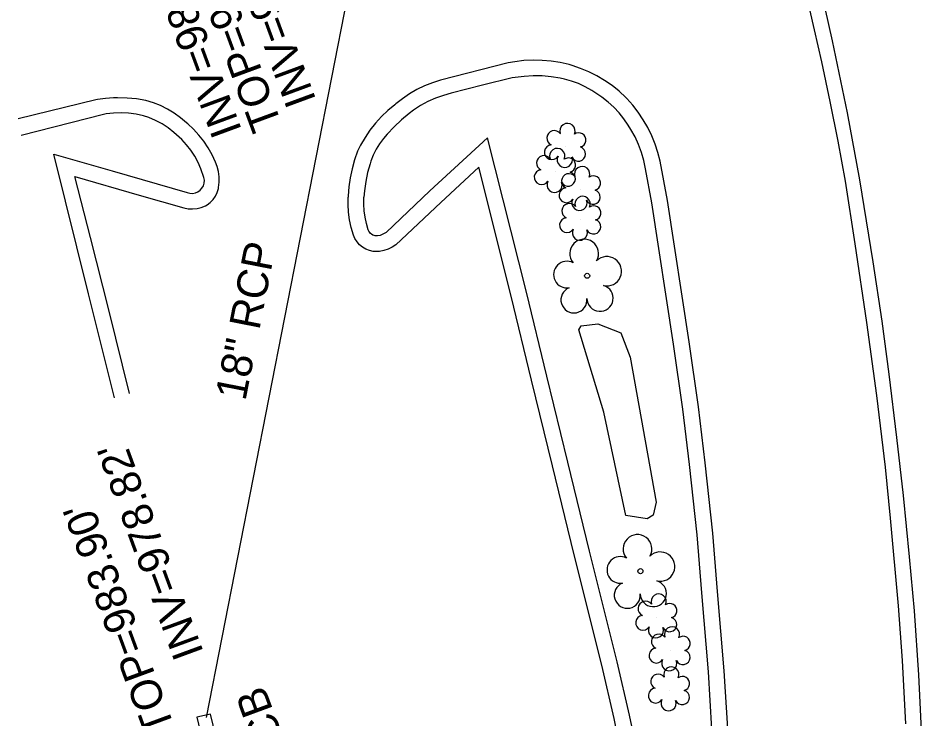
# Model space of a CAD drawing. Extents: x 1611576 to 1617186, y 899279 to 905462.
# Drawn here: x 1615784.5 to 1615902.4, y 904187.9 to 904278.6 of the extents above; entities that cross this region are included whole.
import ezdxf

# ---------------------------------------------------------------- set-up
doc = ezdxf.new("R2010")
doc.units = 0
for name, color, linetype in [('Exist Roads Curbs', 7, 'Continuous'), ('Exist Roads EOP Other', 7, 'Continuous'), ('Exist Structure Minor Catch Basin', 7, 'Continuous'), ('Exist Structure Minor Catch Basin Text', 7, 'Continuous'), ('Exist Structure Minor Catch Basin Top Elevation', 7, 'Continuous'), ('Exist Structure Minor Pipes RCP 18 Inch', 7, 'Continuous'), ('Exist Structure Minor Pipes RCP 18 Inch Invert', 7, 'Continuous'), ('Exist Structure Minor Pipes RCP 18 Inch Text', 7, 'Continuous'), ('Exist Vegetation Hedge Row', 7, 'Continuous'), ('Exist Vegetation Shrub CELL', 7, 'Continuous'), ('Exist Vegetation Tree CELL', 7, 'Continuous')]:
    doc.layers.add(name, color=color, linetype=linetype)

msp = doc.modelspace()

# ---------------------------------------------------------------- linework, layer by layer
at = {"layer": 'Exist Roads Curbs'}
for points in [[(1615893.5, 904257.65), (1615891.93, 904266.36), (1615889.96, 904275.68), (1615887.58, 904286.27), (1615885.87, 904293.7), (1615885.64, 904294.86), (1615885.5, 904296.02), (1615885.43, 904297.19), (1615885.44, 904298.37), (1615885.53, 904299.54), (1615885.57, 904299.9), (1615885.81, 904300.71), (1615886.13, 904301.49), (1615886.52, 904302.24), (1615886.98, 904302.96), (1615887.5, 904303.62), (1615887.72, 904303.86), (1615888.36, 904304.53), (1615889.06, 904305.14), (1615889.8, 904305.68), (1615890.59, 904306.16), (1615891.42, 904306.57), (1615892.28, 904306.9), (1615893.01, 904307.12)], [(1615866.57, 904254.69), (1615865.75, 904259.08), (1615865.52, 904260.15), (1615865.22, 904261.21), (1615864.84, 904262.23), (1615864.39, 904263.23), (1615863.86, 904264.2), (1615863.52, 904264.75), (1615862.96, 904265.57), (1615862.33, 904266.35), (1615861.65, 904267.08), (1615860.91, 904267.74), (1615860.11, 904268.35), (1615859.59, 904268.7), (1615858.79, 904269.24), (1615857.95, 904269.72), (1615857.08, 904270.13), (1615856.17, 904270.46), (1615855.24, 904270.71), (1615854.68, 904270.83), (1615853.52, 904271.01), (1615852.35, 904271.11), (1615851.18, 904271.12), (1615850.01, 904271.06), (1615848.85, 904270.92), (1615848.49, 904270.87), (1615844.63, 904269.92), (1615840.59, 904268.9), (1615839.56, 904268.6), (1615838.55, 904268.24), (1615837.56, 904267.79), (1615836.62, 904267.28), (1615835.71, 904266.7), (1615835.13, 904266.27), (1615834.12, 904265.42), (1615833.17, 904264.52), (1615832.27, 904263.56), (1615831.81, 904263.02), (1615831.3, 904262.34), (1615830.85, 904261.62), (1615830.47, 904260.86), (1615830.17, 904260.07), (1615830.07, 904259.75), (1615829.75, 904258.6), (1615829.51, 904257.43), (1615829.34, 904256.25), (1615829.28, 904255.4)], [(1615796.96, 904229.43), (1615793.58, 904242.9), (1615789.1, 904260.97), (1615796.65, 904258.81), (1615806.38, 904256.02), (1615806.72, 904255.92), (1615807.08, 904255.9), (1615807.44, 904255.97), (1615807.77, 904256.1), (1615808.06, 904256.31), (1615808.3, 904256.58), (1615808.48, 904256.89), (1615808.58, 904257.24), (1615808.61, 904257.6), (1615808.55, 904257.95), (1615808.16, 904259.09), (1615807.8, 904259.93), (1615807.37, 904260.73), (1615806.86, 904261.5), (1615806.3, 904262.21), (1615805.67, 904262.88), (1615805.35, 904263.17), (1615804.66, 904263.81), (1615803.91, 904264.39), (1615803.12, 904264.9), (1615802.29, 904265.35), (1615801.42, 904265.72), (1615800.71, 904265.97), (1615799.76, 904266.17), (1615798.79, 904266.3), (1615797.82, 904266.34), (1615796.85, 904266.31), (1615795.88, 904266.19), (1615795.56, 904266.14), (1615784.86, 904263.42)], [(1615864.09, 904186.33), (1615863.68, 904188.35), (1615862.07, 904195.27), (1615858.48, 904209.6), (1615855.68, 904221.11), (1615852.95, 904232.23), (1615850.32, 904243.11), (1615845.27, 904263.12), (1615837.83, 904256.23), (1615832.14, 904250.86), (1615831.91, 904250.7), (1615831.64, 904250.57), (1615831.36, 904250.47), (1615831.03, 904250.41), (1615830.95, 904250.41), (1615830.74, 904250.42), (1615830.58, 904250.46), (1615830.41, 904250.52), (1615830.27, 904250.61), (1615830.13, 904250.72), (1615830.02, 904250.85), (1615829.93, 904251), (1615829.84, 904251.21), (1615829.6, 904252), (1615829.42, 904252.83), (1615829.3, 904253.67), (1615829.26, 904254.52), (1615829.28, 904255.4)], [(1615899.79, 904096.52), (1615900.18, 904099.49), (1615900.77, 904107.74), (1615901.33, 904116.93), (1615901.83, 904128.29), (1615902.14, 904137.09), (1615902.4, 904145.94), (1615902.44, 904152.54), (1615902.38, 904160.85), (1615902.1, 904171.04), (1615901.84, 904179.09), (1615901.55, 904185.49), (1615901.14, 904193.58), (1615900.6, 904201.84), (1615899.96, 904208.86), (1615899.17, 904216.8), (1615898.31, 904224.32), (1615897.3, 904232.49), (1615896.4, 904239.36), (1615895.25, 904247.03), (1615893.5, 904257.65)], [(1615873.06, 904101.28), (1615873.63, 904112.68), (1615874.39, 904125.07), (1615875.04, 904140.12), (1615875.19, 904147.13), (1615875.17, 904162.5), (1615874.94, 904173.09), (1615874.35, 904186.53), (1615873.89, 904193.95), (1615873.05, 904204.18), (1615872.42, 904211.71), (1615871.45, 904220.8), (1615870.59, 904227.98), (1615869.39, 904236.37), (1615866.57, 904254.69)]]:
    msp.add_lwpolyline(points, dxfattribs=at)
at = {"layer": 'Exist Roads EOP Other'}
for points in [[(1615891.63, 904257.51), (1615890.68, 904262.67), (1615889.66, 904267.81), (1615888.57, 904272.93), (1615887.64, 904277.08), (1615885.33, 904287.12)], [(1615868.6, 904255), (1615867.63, 904260.06), (1615867.35, 904261.19), (1615866.98, 904262.3), (1615866.55, 904263.38), (1615866.04, 904264.43), (1615865.46, 904265.44), (1615864.81, 904266.41), (1615864.1, 904267.33), (1615863.32, 904268.2), (1615863.18, 904268.34), (1615862.32, 904269.13), (1615861.41, 904269.86), (1615860.45, 904270.52), (1615859.45, 904271.12), (1615858.41, 904271.64), (1615857.33, 904272.1), (1615856.23, 904272.48), (1615855.85, 904272.59), (1615854.7, 904272.85), (1615853.54, 904273.03), (1615852.36, 904273.13), (1615851.18, 904273.15), (1615850, 904273.1), (1615848.83, 904272.96), (1615847.96, 904272.81), (1615839.19, 904270.56), (1615838.14, 904270.23), (1615837.12, 904269.82), (1615836.13, 904269.34), (1615835.18, 904268.79), (1615834.27, 904268.17), (1615833.4, 904267.49), (1615833.26, 904267.37), (1615832.38, 904266.64), (1615831.55, 904265.85), (1615830.78, 904265), (1615830.06, 904264.1), (1615829.42, 904263.15), (1615828.84, 904262.16), (1615828.45, 904261.37), (1615828.05, 904260.25), (1615827.73, 904259.1), (1615827.49, 904257.94), (1615827.33, 904256.76), (1615827.24, 904255.58), (1615827.24, 904255.44)], [(1615798.89, 904229.99), (1615796.23, 904240.82), (1615793.88, 904250.2), (1615791.83, 904258.09), (1615800.18, 904255.69), (1615805.95, 904254.02), (1615806.51, 904253.92), (1615807.09, 904253.9), (1615807.66, 904253.96), (1615808.21, 904254.09), (1615808.75, 904254.31), (1615808.96, 904254.42), (1615809.37, 904254.74), (1615809.73, 904255.12), (1615810.03, 904255.56), (1615810.26, 904256.03), (1615810.42, 904256.53), (1615810.45, 904256.67), (1615810.52, 904257.36), (1615810.51, 904258.05), (1615810.42, 904258.73), (1615810.25, 904259.4), (1615810.04, 904259.96), (1615809.61, 904260.89), (1615809.11, 904261.79), (1615808.54, 904262.65), (1615807.9, 904263.46), (1615807.21, 904264.22), (1615806.46, 904264.92), (1615806.28, 904265.06), (1615805.52, 904265.71), (1615804.7, 904266.3), (1615803.84, 904266.82), (1615802.94, 904267.27), (1615802, 904267.65), (1615801.04, 904267.95), (1615801.04, 904267.95), (1615799.82, 904268.15), (1615798.59, 904268.26), (1615797.35, 904268.3), (1615796.83, 904268.29), (1615795.8, 904268.21), (1615794.78, 904268.06), (1615794.53, 904268.01), (1615784.5, 904265.55)], [(1615862.08, 904185.96), (1615861.68, 904187.92), (1615860.09, 904194.8), (1615856.5, 904209.11), (1615853.7, 904220.63), (1615850.97, 904231.74), (1615848.34, 904242.62), (1615844.14, 904259.29), (1615839.22, 904254.75), (1615833.42, 904249.26), (1615832.94, 904248.94), (1615832.42, 904248.68), (1615831.86, 904248.5), (1615831.29, 904248.39), (1615830.97, 904248.37), (1615830.47, 904248.39), (1615829.98, 904248.5), (1615829.52, 904248.68), (1615829.09, 904248.94), (1615828.7, 904249.26), (1615828.38, 904249.63), (1615828.11, 904250.05), (1615827.92, 904250.51), (1615827.91, 904250.52), (1615827.62, 904251.49), (1615827.41, 904252.48), (1615827.27, 904253.47), (1615827.22, 904254.48), (1615827.24, 904255.44)], [(1615899.48, 904187.22), (1615899.03, 904195.42), (1615898.52, 904202.52), (1615897.47, 904213.87), (1615896.81, 904220.44), (1615895.69, 904229.74), (1615894.41, 904239.18), (1615892.92, 904249.38), (1615891.63, 904257.51)], [(1615876.39, 904186.64), (1615875.93, 904194.1), (1615875.09, 904204.35), (1615874.45, 904211.91), (1615873.48, 904221.03), (1615872.62, 904228.25), (1615871.41, 904236.67), (1615868.6, 904255)]]:
    msp.add_lwpolyline(points, dxfattribs=at)
at = {"layer": 'Exist Structure Minor Catch Basin'}
msp.add_lwpolyline([(1615808.34, 904185.18), (1615810.09, 904185.63), (1615809.39, 904188.47), (1615807.64, 904188.07), (1615808.34, 904185.18)], dxfattribs=at)
at = {"layer": 'Exist Structure Minor Pipes RCP 18 Inch'}
msp.add_line((1615808.87, 904188.06), (1615829.26, 904292.17), dxfattribs=at)
msp.add_line((1615808.87, 904188.06), (1615829.26, 904292.17), dxfattribs=at)
at = {"layer": 'Exist Vegetation Hedge Row'}
msp.add_lwpolyline([(1615863.2, 904214.21), (1615860.34, 904227.56), (1615857.1, 904238.23), (1615857.41, 904238.76), (1615859.56, 904239.03), (1615862.53, 904237.85), (1615863.78, 904234.7), (1615867.11, 904215.91), (1615866.72, 904214.24), (1615865.98, 904213.77), (1615863.2, 904214.21)], dxfattribs=at)
at = {"layer": 'Exist Vegetation Shrub CELL'}
for p, q in [((1615855.41, 904261.95), (1615855.41, 904261.95)), ((1615854.09, 904258.71), (1615854.09, 904258.71)), ((1615857.31, 904256.37), (1615857.31, 904256.37)), ((1615857.37, 904252.5), (1615857.37, 904252.5)), ((1615867.22, 904201.01), (1615867.22, 904201.01)), ((1615868.95, 904196.76), (1615868.95, 904196.76)), ((1615868.86, 904191.57), (1615868.86, 904191.57))]:
    msp.add_line(p, q, dxfattribs=at)
for centre, radius, start, end in [((1615855.64, 904263.99), 0.99, 334.8391, 200.4717), ((1615853.93, 904263.07), 0.968, 35.8908, 245.4216), ((1615857.09, 904262.82), 0.929, 284.4567, 126.0861), ((1615853.61, 904261.24), 0.955, 95.1099, 327.9534), ((1615857.05, 904261.02), 0.937, 204.9913, 73.4601), ((1615852.61, 904259.83), 0.968, 35.8908, 245.4216), ((1615854.32, 904260.75), 0.99, 334.8391, 200.4717), ((1615855.29, 904260.26), 0.984, 151.2797, 21.387), ((1615855.76, 904259.57), 0.929, 284.4567, 126.0861), ((1615852.29, 904258), 0.955, 95.1099, 327.9534), ((1615855.83, 904257.49), 0.968, 35.8908, 245.4216), ((1615855.73, 904257.78), 0.937, 204.9913, 73.4601), ((1615857.54, 904258.41), 0.99, 334.8391, 200.4717), ((1615853.96, 904257.02), 0.984, 151.2797, 21.387), ((1615858.99, 904257.24), 0.929, 284.4567, 126.0861), ((1615855.51, 904255.66), 0.955, 95.1099, 327.9534), ((1615858.95, 904255.44), 0.937, 204.9913, 73.4601), ((1615857.19, 904254.68), 0.984, 151.2797, 21.387), ((1615857.6, 904254.54), 0.99, 334.8391, 200.4717), ((1615855.89, 904253.63), 0.968, 35.8908, 245.4216), ((1615859.04, 904253.37), 0.929, 284.4567, 126.0861), ((1615855.57, 904251.8), 0.955, 95.1099, 327.9534), ((1615859.01, 904251.58), 0.937, 204.9913, 73.4601), ((1615857.24, 904250.82), 0.984, 151.2797, 21.387), ((1615867.45, 904203.05), 0.99, 334.8391, 200.4717), ((1615865.74, 904202.14), 0.968, 35.8908, 245.4216), ((1615868.89, 904201.88), 0.929, 284.4567, 126.0861), ((1615865.42, 904200.31), 0.955, 95.1099, 327.9534), ((1615868.86, 904200.08), 0.937, 204.9913, 73.4601), ((1615867.09, 904199.33), 0.984, 151.2797, 21.387), ((1615869.18, 904198.8), 0.99, 334.8391, 200.4717), ((1615867.47, 904197.88), 0.968, 35.8908, 245.4216), ((1615870.62, 904197.63), 0.929, 284.4567, 126.0861), ((1615867.15, 904196.05), 0.955, 95.1099, 327.9534), ((1615870.59, 904195.83), 0.937, 204.9913, 73.4601), ((1615868.82, 904195.07), 0.984, 151.2797, 21.387), ((1615869.09, 904193.61), 0.99, 334.8391, 200.4717), ((1615867.38, 904192.7), 0.968, 35.8908, 245.4216), ((1615870.53, 904192.44), 0.929, 284.4567, 126.0861), ((1615867.06, 904190.87), 0.955, 95.1099, 327.9534), ((1615870.5, 904190.65), 0.937, 204.9913, 73.4601), ((1615868.73, 904189.89), 0.984, 151.2797, 21.387)]:
    msp.add_arc(centre, radius, start, end, dxfattribs=at)
at = {"layer": 'Exist Vegetation Tree CELL'}
for p, q in [((1615858.19, 904245.24), (1615858.19, 904245.24)), ((1615865.09, 904206.99), (1615865.09, 904206.99))]:
    msp.add_line(p, q, dxfattribs=at)
for centre in [(1615858.19, 904245.24), (1615865.09, 904206.99)]:
    msp.add_circle(centre, 0.326, dxfattribs=at)
for centre, radius, start, end in [((1615857.8, 904248.12), 1.86, 330.1651, 219.7134), ((1615860.74, 904245.83), 1.9, 257.1011, 134.1999), ((1615855.58, 904245.4), 1.73, 62.6636, 279.3457), ((1615856.48, 904242.12), 1.69, 111.5671, 6.231), ((1615859.86, 904242.34), 1.7, 181.2822, 74.56), ((1615864.71, 904209.87), 1.86, 330.1651, 219.7134), ((1615862.49, 904207.15), 1.73, 62.6636, 279.3457), ((1615867.64, 904207.58), 1.9, 257.1011, 134.1999), ((1615863.39, 904203.87), 1.69, 111.5671, 6.231), ((1615866.76, 904204.09), 1.7, 181.2822, 74.56)]:
    msp.add_arc(centre, radius, start, end, dxfattribs=at)

# ---------------------------------------------------------------- texts
at = {"layer": 'Exist Structure Minor Catch Basin Text'}
msp.add_text('CB', height=4, rotation=110.2165, dxfattribs=at).set_placement((1615818.87, 904185.39))
at = {"layer": 'Exist Structure Minor Catch Basin Top Elevation'}
for s, p in [("TOP=985.69'", (1615818.69, 904264.82)), ("TOP=983.90'", (1615804.83, 904186.68))]:
    msp.add_text(s, height=4, rotation=110.2165, dxfattribs=at).set_placement(p)
at = {"layer": 'Exist Structure Minor Pipes RCP 18 Inch Invert'}
for s, p in [("INV=981.20'", (1615823.12, 904267.99)), ("INV=980.90'", (1615813.5, 904264.07)), ("INV=978.82'", (1615808.55, 904196.46))]:
    msp.add_text(s, height=4, rotation=110.2165, dxfattribs=at).set_placement(p)
at = {"layer": 'Exist Structure Minor Pipes RCP 18 Inch Text'}
msp.add_text('18" RCP', height=4, rotation=78.9162, dxfattribs=at).set_placement((1615813.92, 904228.94))

doc.saveas('drawing.dxf')
